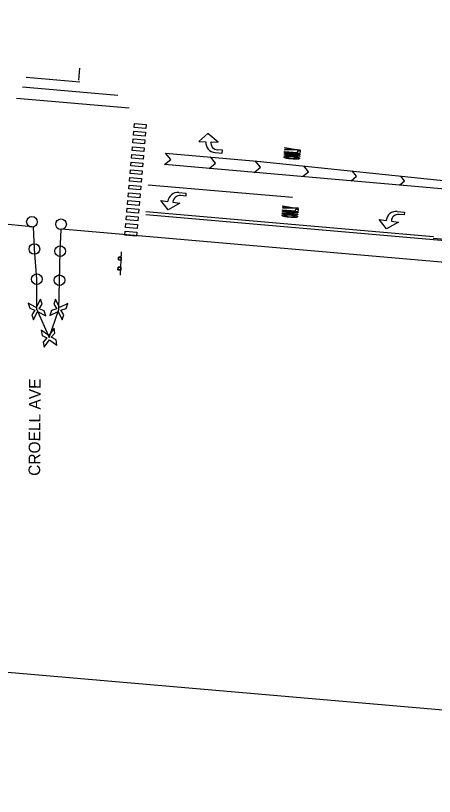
# Model space of a CAD drawing. Extents: x 20499978 to 20505524, y 7953342 to 7954320.
# Drawn here: x 20502533 to 20502749.8, y 7953511.9 to 7953916.1 of the extents above; entities that cross this region are included whole.
import ezdxf

# ---------------------------------------------------------------- set-up
doc = ezdxf.new("R2010")
doc.units = 0
for name, color, linetype in [('Curb', 7, 'Continuous'), ('EdgePaved', 7, 'Continuous'), ('Entrance', 7, 'Continuous'), ('Text', 7, 'Continuous'), ('trf_Cells1', 7, 'Continuous'), ('UtilitiesBelowGround', 7, 'Continuous')]:
    doc.layers.add(name, color=color, linetype=linetype)

msp = doc.modelspace()

# ---------------------------------------------------------------- linework, layer by layer
at = {"layer": 'Curb'}
for p, q in [((20502541.57, 7953806.83), (20502043.56, 7953851.37)), ((20502556.68, 7953805.78), (20503054.78, 7953762.22)), ((20502544.01, 7953763.97), (20502550.29, 7953749.4)), ((20502555.34, 7953763.98), (20502555.34, 7953763.98))]:
    msp.add_line(p, q, dxfattribs=at)
for points in [[(20502544.01, 7953763.97), (20502544.01, 7953763.97), (20502543.98, 7953779.67), (20502542.68, 7953795.29), (20502542.27, 7953806.76)], [(20502550.29, 7953749.4), (20502555.34, 7953763.98), (20502555.7, 7953778.72), (20502556.04, 7953794.12), (20502556.62, 7953805.37)]]:
    msp.add_lwpolyline(points, dxfattribs=at)
at = {"layer": 'EdgePaved'}
for p, q in [((20502566.02, 7953888.88), (20502565.49, 7953882.78)), ((20502566.23, 7953881.71), (20502538.46, 7953884.13)), ((20502585.86, 7953874.74), (20502536.52, 7953879.03)), ((20502591.84, 7953868.18), (20502533.43, 7953873.28)), ((20502594.42, 7953858.23), (20502594.6, 7953860.23)), ((20502600.4, 7953857.71), (20502594.42, 7953858.23)), ((20502594.6, 7953860.23), (20502600.58, 7953859.71)), ((20502600.58, 7953859.71), (20502600.4, 7953857.71)), ((20502594.08, 7953854.25), (20502594.25, 7953856.24)), ((20502600.06, 7953853.73), (20502594.08, 7953854.25)), ((20502594.25, 7953856.24), (20502600.23, 7953855.72)), ((20502600.23, 7953855.72), (20502600.06, 7953853.73)), ((20502593.73, 7953850.26), (20502593.9, 7953852.26)), ((20502599.71, 7953849.74), (20502593.73, 7953850.26)), ((20502593.9, 7953852.26), (20502599.88, 7953851.74)), ((20502599.88, 7953851.74), (20502599.71, 7953849.74)), ((20502593.04, 7953842.3), (20502593.21, 7953844.29)), ((20502593.21, 7953844.29), (20502599.19, 7953843.77)), ((20502593.38, 7953846.28), (20502593.56, 7953848.27)), ((20502599.36, 7953845.76), (20502593.38, 7953846.28)), ((20502593.56, 7953848.27), (20502599.54, 7953847.75)), ((20502599.54, 7953847.75), (20502599.36, 7953845.76)), ((20502613.3, 7953841.72), (20502610.58, 7953844.97)), ((20502610.6, 7953844.97), (20502660, 7953840.67)), ((20502592.7, 7953838.32), (20502592.87, 7953840.32)), ((20502592.87, 7953840.32), (20502598.85, 7953839.8)), ((20502599.01, 7953841.77), (20502593.04, 7953842.3)), ((20502599.19, 7953843.77), (20502599.01, 7953841.77)), ((20502610.06, 7953839), (20502613.3, 7953841.72)), ((20502636.53, 7953839.7), (20502633.8, 7953842.95)), ((20502659.75, 7953837.68), (20502657.02, 7953840.93)), ((20502659.73, 7953840.69), (20502958.13, 7953809.28)), ((20502592.35, 7953834.34), (20502592.53, 7953836.33)), ((20502592.53, 7953836.33), (20502598.51, 7953835.81)), ((20502598.68, 7953837.8), (20502592.7, 7953838.32)), ((20502598.85, 7953839.8), (20502598.68, 7953837.8)), ((20502794.63, 7953822.92), (20502610.06, 7953839)), ((20502633.28, 7953836.97), (20502636.53, 7953839.7)), ((20502656.5, 7953834.95), (20502659.75, 7953837.68)), ((20502592.01, 7953830.35), (20502592.18, 7953832.35)), ((20502592.18, 7953832.35), (20502598.16, 7953831.83)), ((20502598.33, 7953833.82), (20502592.35, 7953834.34)), ((20502598.51, 7953835.81), (20502598.33, 7953833.82)), ((20502591.66, 7953826.37), (20502591.83, 7953828.36)), ((20502591.83, 7953828.36), (20502597.81, 7953827.84)), ((20502597.99, 7953829.83), (20502592.01, 7953830.35)), ((20502598.16, 7953831.83), (20502597.99, 7953829.83)), ((20502676.33, 7953821.89), (20502601.66, 7953828.4)), ((20502591.31, 7953822.38), (20502591.49, 7953824.38)), ((20502591.49, 7953824.38), (20502597.47, 7953823.86)), ((20502597.64, 7953825.85), (20502591.66, 7953826.37)), ((20502597.81, 7953827.84), (20502597.64, 7953825.85)), ((20502590.97, 7953818.4), (20502591.14, 7953820.39)), ((20502591.14, 7953820.39), (20502597.12, 7953819.87)), ((20502597.29, 7953821.86), (20502591.31, 7953822.38)), ((20502597.47, 7953823.86), (20502597.29, 7953821.86)), ((20502590.61, 7953814.42), (20502590.78, 7953816.41)), ((20502590.78, 7953816.41), (20502596.76, 7953815.89)), ((20502596.95, 7953817.88), (20502590.97, 7953818.4)), ((20502597.12, 7953819.87), (20502596.95, 7953817.88)), ((20502590.26, 7953810.43), (20502590.43, 7953812.42)), ((20502590.43, 7953812.42), (20502596.41, 7953811.9)), ((20502596.59, 7953813.9), (20502590.61, 7953814.42)), ((20502596.76, 7953815.89), (20502596.59, 7953813.9)), ((20502803.88, 7953795.31), (20502600.33, 7953813.03)), ((20502749.3, 7953801.57), (20502600.46, 7953814.52)), ((20502589.9, 7953806.45), (20502590.08, 7953808.44)), ((20502590.08, 7953808.44), (20502596.05, 7953807.92)), ((20502596.24, 7953809.91), (20502590.26, 7953810.43)), ((20502596.05, 7953807.92), (20502595.88, 7953805.93)), ((20502596.41, 7953811.9), (20502596.24, 7953809.91)), ((20502589.55, 7953802.46), (20502589.73, 7953804.45)), ((20502589.73, 7953804.45), (20502595.71, 7953803.93)), ((20502595.88, 7953805.93), (20502589.9, 7953806.45)), ((20502595.71, 7953803.93), (20502595.53, 7953801.94)), ((20502595.53, 7953801.94), (20502589.55, 7953802.46))]:
    msp.add_line(p, q, dxfattribs=at)
for points in [[(20502681.56, 7953832.77), (20502684.63, 7953835.31), (20502682.13, 7953838.33)], [(20502706.66, 7953830.58), (20502709.52, 7953832.94), (20502707.25, 7953835.69)], [(20502731.77, 7953828.39), (20502734.41, 7953830.57), (20502732.36, 7953833.05)], [(20502993.37, 7953780.25), (20502803.95, 7953796.06), (20502749.23, 7953800.82)]]:
    msp.add_lwpolyline(points, dxfattribs=at)
at = {"layer": 'Entrance'}
for p, q in [((20502631.52, 7953850.86), (20502631.51, 7953850.68)), ((20502634.13, 7953850.45), (20502634.15, 7953850.76)), ((20502611.82, 7953819.84), (20502611.84, 7953820.03)), ((20502614.46, 7953819.8), (20502614.43, 7953819.49)), ((20502724.92, 7953810.06), (20502724.94, 7953810.24)), ((20502727.55, 7953810.01), (20502727.53, 7953809.7)), ((20502587.24, 7953781.78), (20502587.84, 7953793.76)), ((20502587.63, 7953789.59), (20502587.7, 7953790.99)), ((20502587.37, 7953784.45), (20502587.44, 7953785.85)), ((20502545.85, 7953769.28), (20502543.66, 7953765.04)), ((20502546.69, 7953766.66), (20502545.85, 7953769.28)), ((20502553.59, 7953769.33), (20502552.71, 7953766.72)), ((20502555.7, 7953765.05), (20502553.59, 7953769.33)), ((20502543.66, 7953765.04), (20502539.42, 7953767.22)), ((20502539.42, 7953767.22), (20502540.26, 7953764.6)), ((20502540.26, 7953764.6), (20502542.94, 7953763.62)), ((20502542.94, 7953763.62), (20502541.33, 7953761.27)), ((20502545.08, 7953764.31), (20502546.69, 7953766.66)), ((20502547.76, 7953763.33), (20502545.08, 7953764.31)), ((20502551.58, 7953763.41), (20502550.7, 7953760.8)), ((20502554.28, 7953764.34), (20502551.58, 7953763.41)), ((20502552.71, 7953766.72), (20502554.28, 7953764.34)), ((20502559.98, 7953767.16), (20502555.7, 7953765.05)), ((20502556.41, 7953763.62), (20502559.1, 7953764.55)), ((20502557.98, 7953761.24), (20502556.41, 7953763.62)), ((20502559.1, 7953764.55), (20502559.98, 7953767.16)), ((20502541.33, 7953761.27), (20502542.17, 7953758.65)), ((20502542.17, 7953758.65), (20502544.35, 7953762.9)), ((20502544.35, 7953762.9), (20502548.6, 7953760.71)), ((20502548.6, 7953760.71), (20502547.76, 7953763.33)), ((20502550.7, 7953760.8), (20502554.98, 7953762.92)), ((20502554.98, 7953762.92), (20502557.09, 7953758.64)), ((20502557.09, 7953758.64), (20502557.98, 7953761.24)), ((20502550.11, 7953750.51), (20502546.24, 7953753.3)), ((20502546.24, 7953753.3), (20502546.68, 7953750.59)), ((20502552.91, 7953754.38), (20502550.11, 7953750.51)), ((20502551.4, 7953749.58), (20502553.34, 7953751.66)), ((20502553.34, 7953751.66), (20502552.91, 7953754.38)), ((20502546.68, 7953750.59), (20502549.18, 7953749.22)), ((20502549.18, 7953749.22), (20502547.24, 7953747.13)), ((20502547.67, 7953744.42), (20502550.47, 7953748.29)), ((20502550.47, 7953748.29), (20502554.34, 7953745.49)), ((20502553.9, 7953748.21), (20502551.4, 7953749.58)), ((20502554.34, 7953745.49), (20502553.9, 7953748.21)), ((20502547.24, 7953747.13), (20502547.67, 7953744.42))]:
    msp.add_line(p, q, dxfattribs=at)
for points in [[(20502632.42, 7953855.1), (20502627.84, 7953851), (20502631.52, 7953850.86)], [(20502632.42, 7953855.1), (20502627.84, 7953851), (20502631.52, 7953850.86)], [(20502634.15, 7953850.76), (20502637.84, 7953850.63), (20502632.42, 7953855.1)], [(20502634.15, 7953850.76), (20502637.84, 7953850.63), (20502632.42, 7953855.1)], [(20502631.52, 7953850.86), (20502631.51, 7953850.68)], [(20502634.13, 7953850.45), (20502634.15, 7953850.76)], [(20502636.31, 7953845.26), (20502639.98, 7953844.94), (20502640.11, 7953846.43), (20502637.49, 7953846.66)], [(20502636.31, 7953845.26), (20502639.98, 7953844.94), (20502640.11, 7953846.43), (20502637.49, 7953846.66)], [(20502617.51, 7953824.53), (20502621.17, 7953824.21), (20502621.04, 7953822.72), (20502618.42, 7953822.95)], [(20502617.51, 7953824.53), (20502621.17, 7953824.21), (20502621.04, 7953822.72), (20502618.42, 7953822.95)], [(20502611.97, 7953815.52), (20502608.17, 7953820.35), (20502611.82, 7953819.84)], [(20502611.97, 7953815.52), (20502608.17, 7953820.35), (20502611.82, 7953819.84)], [(20502611.82, 7953819.84), (20502611.84, 7953820.03)], [(20502614.43, 7953819.49), (20502618.08, 7953818.98), (20502611.97, 7953815.52)], [(20502614.43, 7953819.49), (20502618.08, 7953818.98), (20502611.97, 7953815.52)], [(20502614.46, 7953819.8), (20502614.43, 7953819.49)], [(20502730.6, 7953814.75), (20502734.27, 7953814.43), (20502734.14, 7953812.94), (20502731.52, 7953813.17)], [(20502730.6, 7953814.75), (20502734.27, 7953814.43), (20502734.14, 7953812.94), (20502731.52, 7953813.17)], [(20502725.07, 7953805.73), (20502721.27, 7953810.56), (20502724.92, 7953810.06)], [(20502725.07, 7953805.73), (20502721.27, 7953810.56), (20502724.92, 7953810.06)], [(20502724.92, 7953810.06), (20502724.94, 7953810.24)], [(20502727.53, 7953809.7), (20502731.18, 7953809.2), (20502725.07, 7953805.73)], [(20502727.53, 7953809.7), (20502731.18, 7953809.2), (20502725.07, 7953805.73)], [(20502727.55, 7953810.01), (20502727.53, 7953809.7)], [(20502587.7, 7953790.99), (20502586.3, 7953791.06), (20502586.23, 7953789.66), (20502587.63, 7953789.59)], [(20502587.44, 7953785.85), (20502586.04, 7953785.92), (20502585.97, 7953784.52), (20502587.37, 7953784.45)]]:
    msp.add_lwpolyline(points, dxfattribs=at)
for points in [[(20502587.7, 7953790.99), (20502587.63, 7953789.59), (20502586.23, 7953789.66), (20502586.3, 7953791.06)], [(20502587.44, 7953785.85), (20502587.37, 7953784.45), (20502585.97, 7953784.52), (20502586.04, 7953785.92)]]:
    msp.add_lwpolyline(points, close=True, dxfattribs=at)
for centre in [(20502541.43, 7953809.38), (20502556.5, 7953808.11), (20502542.68, 7953795.29), (20502556.05, 7953794.2), (20502543.98, 7953779.67), (20502555.7, 7953779.13)]:
    msp.add_circle(centre, 2.75, dxfattribs=at)
for centre, major_axis, start_param, end_param in [((20502636.74, 7953850.22), (5.24, -0.46), 3.141593, 4.712389), ((20502636.74, 7953850.22), (5.24, -0.46), 3.141593, 4.712389), ((20502637.79, 7953850.13), (3.67, -0.32), 3.141593, 4.712389), ((20502637.79, 7953850.13), (3.67, -0.32), 3.141593, 4.712389), ((20502617.07, 7953819.57), (5.24, -0.46), 1.570796, 3.141593), ((20502617.07, 7953819.57), (5.24, -0.46), 1.570796, 3.141593), ((20502618.12, 7953819.48), (3.67, -0.32), 1.570796, 3.141593), ((20502618.12, 7953819.48), (3.67, -0.32), 1.570796, 3.141593), ((20502730.17, 7953809.78), (5.24, -0.46), 1.570796, 3.141593), ((20502730.17, 7953809.78), (5.24, -0.46), 1.570796, 3.141593), ((20502731.22, 7953809.69), (3.67, -0.32), 1.570796, 3.141593), ((20502731.22, 7953809.69), (3.67, -0.32), 1.570796, 3.141593)]:
    msp.add_ellipse(centre, major_axis=major_axis, ratio=0.9474, start_param=start_param, end_param=end_param, dxfattribs=at)
at = {"layer": 'Text'}
msp.add_lwpolyline([(20501752.19, 7954145.12), (20503313.82, 7954010.01), (20503270.73, 7953511.87), (20501709.09, 7953646.98)], close=True, dxfattribs=at)
at = {"layer": 'trf_Cells1'}
for p, q in [((20502676.76, 7953841.85), (20502675.17, 7953841.99)), ((20502675.19, 7953842.31), (20502676.79, 7953842.17)), ((20502676.84, 7953842.81), (20502675.25, 7953842.94)), ((20502675.27, 7953843.26), (20502676.87, 7953843.13)), ((20502674.13, 7953812.15), (20502675.73, 7953812.02)), ((20502675.78, 7953812.65), (20502674.19, 7953812.79)), ((20502674.21, 7953813.11), (20502675.81, 7953812.97)), ((20502675.7, 7953811.7), (20502674.11, 7953811.83))]:
    msp.add_line(p, q, dxfattribs=at)
for points in [[(20502680.09, 7953843.19), (20502672.11, 7953843.85), (20502672.14, 7953844.17), (20502677.29, 7953844.38), (20502672.19, 7953844.81), (20502672.22, 7953845.13), (20502680.19, 7953844.46), (20502680.16, 7953844.14), (20502675.01, 7953843.93), (20502680.11, 7953843.51)], [(20502680.22, 7953844.78), (20502672.25, 7953845.45), (20502672.27, 7953845.77), (20502678.97, 7953845.21), (20502679.05, 7953846.16), (20502680.32, 7953846.06)], [(20502672.34, 7953846.56), (20502672.37, 7953846.88), (20502675.58, 7953846.93), (20502672.42, 7953847.52), (20502672.45, 7953847.84), (20502677.19, 7953846.96), (20502680.38, 7953846.69), (20502680.35, 7953846.38), (20502677.16, 7953846.64)], [(20502679.16, 7953814.63), (20502671.18, 7953815.29), (20502671.21, 7953815.61), (20502677.91, 7953815.05), (20502677.99, 7953816.01), (20502679.26, 7953815.9)], [(20502671.28, 7953816.41), (20502671.3, 7953816.73), (20502674.52, 7953816.78), (20502671.36, 7953817.36), (20502671.38, 7953817.68), (20502676.13, 7953816.8), (20502679.32, 7953816.54), (20502679.29, 7953816.22), (20502676.1, 7953816.49)], [(20502679.02, 7953813.03), (20502671.05, 7953813.7), (20502671.08, 7953814.02), (20502676.23, 7953814.23), (20502671.13, 7953814.65), (20502671.16, 7953814.97), (20502679.13, 7953814.31), (20502679.1, 7953813.99), (20502673.95, 7953813.78), (20502679.05, 7953813.35)]]:
    msp.add_lwpolyline(points, close=True, dxfattribs=at)
for points in [[(20502672.03, 7953842.89), (20502672.04, 7953842.94), (20502672.06, 7953842.99), (20502672.08, 7953843.03), (20502672.11, 7953843.08), (20502672.18, 7953843.13), (20502672.28, 7953843.17), (20502672.42, 7953843.22), (20502672.57, 7953843.25), (20502672.7, 7953843.27), (20502672.83, 7953843.29), (20502672.97, 7953843.3), (20502673.11, 7953843.32), (20502673.25, 7953843.32), (20502673.38, 7953843.33), (20502673.48, 7953843.33), (20502673.58, 7953843.33), (20502673.79, 7953843.33), (20502673.94, 7953843.33), (20502674.08, 7953843.33), (20502674.24, 7953843.32), (20502674.39, 7953843.32), (20502674.6, 7953843.31), (20502674.78, 7953843.3), (20502675.08, 7953843.28), (20502675.27, 7953843.26)], [(20502675.17, 7953841.99), (20502674.97, 7953842.01), (20502674.67, 7953842.03), (20502674.5, 7953842.06), (20502674.28, 7953842.08), (20502674.14, 7953842.1), (20502673.98, 7953842.12), (20502673.85, 7953842.14), (20502673.69, 7953842.17), (20502673.49, 7953842.2), (20502673.39, 7953842.22), (20502673.29, 7953842.24), (20502673.16, 7953842.26), (20502673.02, 7953842.29), (20502672.89, 7953842.33), (20502672.75, 7953842.37), (20502672.63, 7953842.4), (20502672.5, 7953842.45), (20502672.36, 7953842.51), (20502672.23, 7953842.57), (20502672.14, 7953842.63), (20502672.08, 7953842.69), (20502672.06, 7953842.74), (20502672.04, 7953842.79), (20502672.03, 7953842.84), (20502672.03, 7953842.89)], [(20502675.25, 7953842.94), (20502675.09, 7953842.95), (20502674.86, 7953842.97), (20502674.56, 7953842.98), (20502674.29, 7953842.99), (20502674.04, 7953842.99), (20502673.83, 7953842.99), (20502673.65, 7953842.97), (20502673.49, 7953842.94), (20502673.4, 7953842.91), (20502673.34, 7953842.86), (20502673.31, 7953842.78)], [(20502673.31, 7953842.78), (20502673.32, 7953842.7), (20502673.38, 7953842.65), (20502673.46, 7953842.6), (20502673.62, 7953842.55), (20502673.79, 7953842.5), (20502673.99, 7953842.46), (20502674.24, 7953842.42), (20502674.51, 7953842.38), (20502674.81, 7953842.35), (20502675.04, 7953842.32), (20502675.19, 7953842.31)], [(20502680, 7953842.23), (20502680, 7953842.17), (20502679.98, 7953842.13), (20502679.96, 7953842.08), (20502679.92, 7953842.04), (20502679.86, 7953841.99), (20502679.76, 7953841.94), (20502679.62, 7953841.9), (20502679.47, 7953841.87), (20502679.33, 7953841.84), (20502679.21, 7953841.83), (20502679.07, 7953841.81), (20502678.93, 7953841.8), (20502678.79, 7953841.8), (20502678.65, 7953841.79), (20502678.56, 7953841.79), (20502678.46, 7953841.79), (20502678.25, 7953841.79), (20502678.09, 7953841.79), (20502677.96, 7953841.79), (20502677.79, 7953841.79), (20502677.65, 7953841.8), (20502677.44, 7953841.81), (20502677.26, 7953841.82), (20502676.96, 7953841.84), (20502676.76, 7953841.85)], [(20502676.79, 7953842.17), (20502676.94, 7953842.16), (20502677.17, 7953842.15), (20502677.48, 7953842.14), (20502677.74, 7953842.13), (20502678, 7953842.12), (20502678.21, 7953842.13), (20502678.38, 7953842.15), (20502678.54, 7953842.18), (20502678.64, 7953842.21), (20502678.7, 7953842.26), (20502678.73, 7953842.33)], [(20502678.73, 7953842.33), (20502678.71, 7953842.41), (20502678.66, 7953842.47), (20502678.57, 7953842.52), (20502678.42, 7953842.57), (20502678.25, 7953842.62), (20502678.04, 7953842.66), (20502677.79, 7953842.7), (20502677.53, 7953842.73), (20502677.22, 7953842.77), (20502677, 7953842.79), (20502676.84, 7953842.81)], [(20502676.87, 7953843.13), (20502677.07, 7953843.11), (20502677.36, 7953843.08), (20502677.54, 7953843.06), (20502677.75, 7953843.04), (20502677.89, 7953843.02), (20502678.06, 7953842.99), (20502678.19, 7953842.97), (20502678.35, 7953842.95), (20502678.55, 7953842.92), (20502678.65, 7953842.89), (20502678.75, 7953842.88), (20502678.87, 7953842.85), (20502679.02, 7953842.82), (20502679.15, 7953842.79), (20502679.29, 7953842.75), (20502679.41, 7953842.71), (20502679.53, 7953842.67), (20502679.68, 7953842.61), (20502679.81, 7953842.55), (20502679.9, 7953842.49), (20502679.95, 7953842.43), (20502679.98, 7953842.37), (20502680, 7953842.33), (20502680.01, 7953842.28), (20502680, 7953842.23)], [(20502670.97, 7953812.74), (20502670.98, 7953812.79), (20502670.99, 7953812.83), (20502671.02, 7953812.88), (20502671.05, 7953812.92), (20502671.12, 7953812.97), (20502671.22, 7953813.02), (20502671.36, 7953813.06), (20502671.51, 7953813.09), (20502671.64, 7953813.12), (20502671.77, 7953813.13), (20502671.91, 7953813.15), (20502672.05, 7953813.16), (20502672.19, 7953813.17), (20502672.32, 7953813.17), (20502672.42, 7953813.17), (20502672.52, 7953813.17), (20502672.73, 7953813.17), (20502672.88, 7953813.17), (20502673.02, 7953813.17), (20502673.18, 7953813.17), (20502673.33, 7953813.16), (20502673.54, 7953813.15), (20502673.72, 7953813.14), (20502674.01, 7953813.12), (20502674.21, 7953813.11)], [(20502674.11, 7953811.83), (20502673.91, 7953811.85), (20502673.61, 7953811.88), (20502673.44, 7953811.9), (20502673.22, 7953811.92), (20502673.08, 7953811.94), (20502672.92, 7953811.97), (20502672.78, 7953811.99), (20502672.63, 7953812.01), (20502672.43, 7953812.05), (20502672.33, 7953812.07), (20502672.23, 7953812.08), (20502672.1, 7953812.11), (20502671.96, 7953812.14), (20502671.82, 7953812.17), (20502671.69, 7953812.21), (20502671.57, 7953812.25), (20502671.44, 7953812.29), (20502671.3, 7953812.35), (20502671.17, 7953812.42), (20502671.08, 7953812.47), (20502671.02, 7953812.54), (20502671, 7953812.59), (20502670.98, 7953812.63), (20502670.97, 7953812.68), (20502670.97, 7953812.74)], [(20502674.19, 7953812.79), (20502674.03, 7953812.8), (20502673.8, 7953812.81), (20502673.5, 7953812.83), (20502673.23, 7953812.83), (20502672.98, 7953812.84), (20502672.77, 7953812.83), (20502672.59, 7953812.81), (20502672.43, 7953812.78), (20502672.34, 7953812.75), (20502672.28, 7953812.71), (20502672.25, 7953812.63)], [(20502672.25, 7953812.63), (20502672.26, 7953812.55), (20502672.32, 7953812.49), (20502672.4, 7953812.44), (20502672.56, 7953812.39), (20502672.73, 7953812.34), (20502672.93, 7953812.3), (20502673.18, 7953812.26), (20502673.45, 7953812.23), (20502673.75, 7953812.19), (20502673.98, 7953812.17), (20502674.13, 7953812.15)], [(20502678.94, 7953812.07), (20502678.94, 7953812.02), (20502678.92, 7953811.97), (20502678.9, 7953811.93), (20502678.86, 7953811.88), (20502678.8, 7953811.83), (20502678.7, 7953811.79), (20502678.56, 7953811.74), (20502678.41, 7953811.71), (20502678.27, 7953811.69), (20502678.15, 7953811.67), (20502678.01, 7953811.66), (20502677.87, 7953811.64), (20502677.72, 7953811.64), (20502677.59, 7953811.64), (20502677.49, 7953811.63), (20502677.4, 7953811.63), (20502677.19, 7953811.63), (20502677.03, 7953811.63), (20502676.9, 7953811.63), (20502676.73, 7953811.64), (20502676.59, 7953811.64), (20502676.38, 7953811.65), (20502676.2, 7953811.66), (20502675.9, 7953811.68), (20502675.7, 7953811.7)], [(20502675.73, 7953812.02), (20502675.88, 7953812.01), (20502676.11, 7953811.99), (20502676.42, 7953811.98), (20502676.68, 7953811.97), (20502676.94, 7953811.97), (20502677.15, 7953811.97), (20502677.32, 7953811.99), (20502677.48, 7953812.02), (20502677.58, 7953812.05), (20502677.64, 7953812.1), (20502677.67, 7953812.18)], [(20502677.67, 7953812.18), (20502677.65, 7953812.26), (20502677.6, 7953812.32), (20502677.51, 7953812.36), (20502677.36, 7953812.41), (20502677.19, 7953812.46), (20502676.98, 7953812.5), (20502676.73, 7953812.54), (20502676.47, 7953812.58), (20502676.16, 7953812.61), (20502675.94, 7953812.64), (20502675.78, 7953812.65)], [(20502675.81, 7953812.97), (20502676.01, 7953812.95), (20502676.3, 7953812.93), (20502676.48, 7953812.91), (20502676.69, 7953812.88), (20502676.83, 7953812.86), (20502677, 7953812.84), (20502677.13, 7953812.82), (20502677.29, 7953812.79), (20502677.49, 7953812.76), (20502677.59, 7953812.74), (20502677.68, 7953812.72), (20502677.81, 7953812.7), (20502677.95, 7953812.67), (20502678.09, 7953812.63), (20502678.23, 7953812.59), (20502678.35, 7953812.56), (20502678.47, 7953812.51), (20502678.62, 7953812.45), (20502678.75, 7953812.39), (20502678.84, 7953812.33), (20502678.89, 7953812.27), (20502678.92, 7953812.22), (20502678.94, 7953812.17), (20502678.95, 7953812.12), (20502678.94, 7953812.07)]]:
    msp.add_spline(points, degree=3, dxfattribs=at)

# ---------------------------------------------------------------- texts
at = {"layer": 'UtilitiesBelowGround'}
msp.add_text('CROELL AVE', height=6, rotation=89.6519, dxfattribs=at).set_placement((20502545.65, 7953677.82))

doc.saveas('drawing.dxf')
